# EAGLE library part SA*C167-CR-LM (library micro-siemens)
16 bit Microcontroller
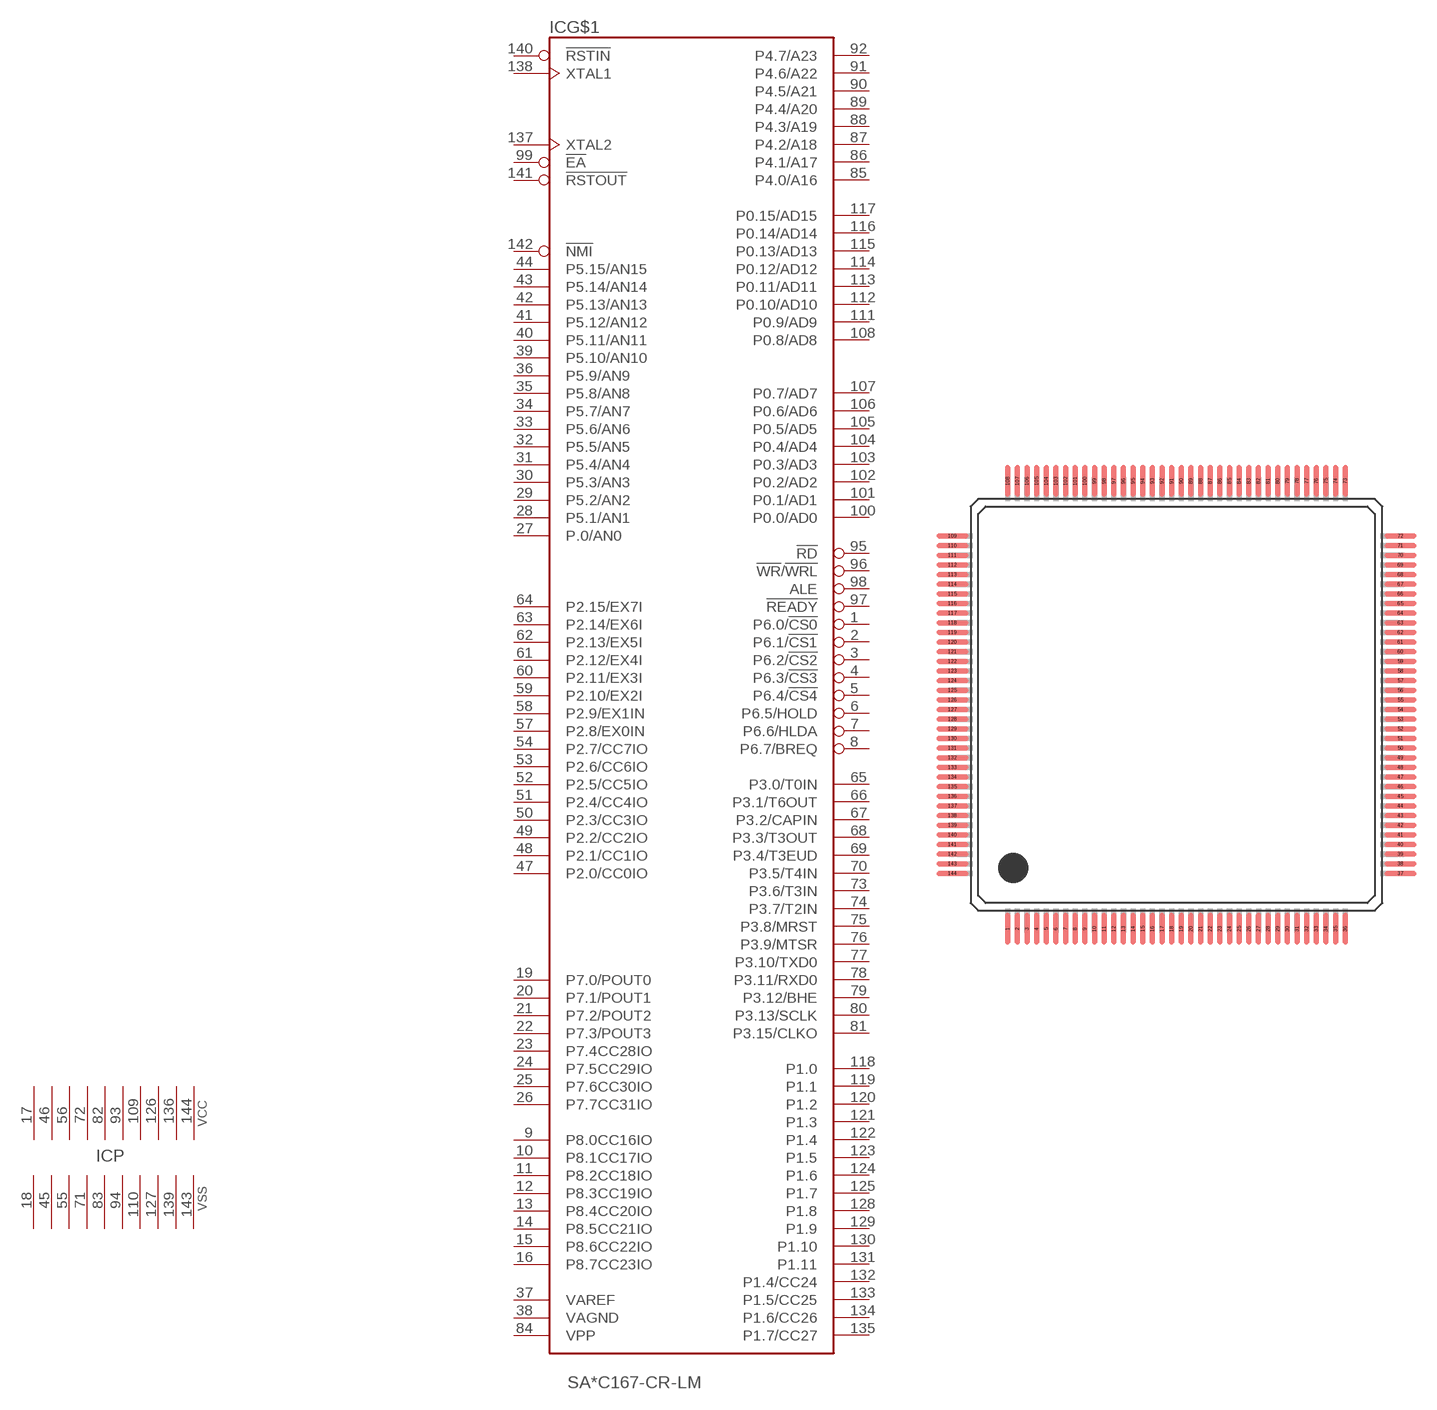
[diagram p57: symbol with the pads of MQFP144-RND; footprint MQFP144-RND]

Designator prefix IC; gates G$1=C167-2 P=10VCCVSS-1

## SABC167-CR-LM (OC_FARNELL: unknown; OC_NEWARK: unknown), SAFC167-CR-LM (OC_FARNELL: unknown; OC_NEWARK: unknown), SAKC167-CR-LM (OC_FARNELL: unknown; OC_NEWARK: unknown)  [MQFP144-RND]
1  G$1:P6.0/!CS0
2  G$1:P6.1/!CS1
3  G$1:P6.2/!CS2
4  G$1:P6.3/!CS3
5  G$1:P6.4/!CS4
6  G$1:P6.5/HOLD
7  G$1:P6.6/HLDA
8  G$1:P6.7/BREQ
9  G$1:P8.0CC16IO
10  G$1:P8.1CC17IO
11  G$1:P8.2CC18IO
12  G$1:P8.3CC19IO
13  G$1:P8.4CC20IO
14  G$1:P8.5CC21IO
15  G$1:P8.6CC22IO
16  G$1:P8.7CC23IO
17  P:VCC  pwr
18  P:VSS  pwr
19  G$1:P7.0/POUT0
20  G$1:P7.1/POUT1
21  G$1:P7.2/POUT2
22  G$1:P7.3/POUT3
23  G$1:P7.4CC28IO
24  G$1:P7.5CC29IO
25  G$1:P7.6CC30IO
26  G$1:P7.7CC31IO
27  G$1:P.0/AN0  in
28  G$1:P5.1/AN1  in
29  G$1:P5.2/AN2  in
30  G$1:P5.3/AN3  in
31  G$1:P5.4/AN4  in
32  G$1:P5.5/AN5  in
33  G$1:P5.6/AN6  in
34  G$1:P5.7/AN7  in
35  G$1:P5.8/AN8  in
36  G$1:P5.9/AN9  in
37  G$1:VAREF  pas
38  G$1:VAGND  pas
39  G$1:P5.10/AN10  in
40  G$1:P5.11/AN11  in
41  G$1:P5.12/AN12  in
42  G$1:P5.13/AN13  in
43  G$1:P5.14/AN14  in
44  G$1:P5.15/AN15  in
45  P:VSS  pwr
46  P:VCC  pwr
47  G$1:P2.0/CC0IO
48  G$1:P2.1/CC1IO
49  G$1:P2.2/CC2IO
50  G$1:P2.3/CC3IO
51  G$1:P2.4/CC4IO
52  G$1:P2.5/CC5IO
53  G$1:P2.6/CC6IO
54  G$1:P2.7/CC7IO
55  P:VSS  pwr
56  P:VCC  pwr
57  G$1:P2.8/EX0IN
58  G$1:P2.9/EX1IN
59  G$1:P2.10/EX2I
60  G$1:P2.11/EX3I
61  G$1:P2.12/EX4I
62  G$1:P2.13/EX5I
63  G$1:P2.14/EX6I
64  G$1:P2.15/EX7I
65  G$1:P3.0/T0IN
66  G$1:P3.1/T6OUT
67  G$1:P3.2/CAPIN
68  G$1:P3.3/T3OUT
69  G$1:P3.4/T3EUD
70  G$1:P3.5/T4IN
71  P:VSS  pwr
72  P:VCC  pwr
73  G$1:P3.6/T3IN
74  G$1:P3.7/T2IN
75  G$1:P3.8/MRST
76  G$1:P3.9/MTSR
77  G$1:P3.10/TXD0
78  G$1:P3.11/RXD0
79  G$1:P3.12/BHE
80  G$1:P3.13/SCLK
81  G$1:P3.15/CLKO
82  P:VCC  pwr
83  P:VSS  pwr
84  G$1:VPP  pas
85  G$1:P4.0/A16
86  G$1:P4.1/A17
87  G$1:P4.2/A18
88  G$1:P4.3/A19
89  G$1:P4.4/A20
90  G$1:P4.5/A21
91  G$1:P4.6/A22
92  G$1:P4.7/A23
93  P:VCC  pwr
94  P:VSS  pwr
95  G$1:!RD  out
96  G$1:!WR!/!WRL  out
97  G$1:!READY  in
98  G$1:ALE  out
99  G$1:!EA  in
100  G$1:P0.0/AD0
101  G$1:P0.1/AD1
102  G$1:P0.2/AD2
103  G$1:P0.3/AD3
104  G$1:P0.4/AD4
105  G$1:P0.5/AD5
106  G$1:P0.6/AD6
107  G$1:P0.7/AD7
108  G$1:P0.8/AD8
109  P:VCC  pwr
110  P:VSS  pwr
111  G$1:P0.9/AD9
112  G$1:P0.10/AD10
113  G$1:P0.11/AD11
114  G$1:P0.12/AD12
115  G$1:P0.13/AD13
116  G$1:P0.14/AD14
117  G$1:P0.15/AD15
118  G$1:P1.0
119  G$1:P1.1
120  G$1:P1.2
121  G$1:P1.3
122  G$1:P1.4
123  G$1:P1.5
124  G$1:P1.6
125  G$1:P1.7
126  P:VCC  pwr
127  P:VSS  pwr
128  G$1:P1.8
129  G$1:P1.9
130  G$1:P1.10
131  G$1:P1.11
132  G$1:P1.4/CC24
133  G$1:P1.5/CC25
134  G$1:P1.6/CC26
135  G$1:P1.7/CC27
136  P:VCC  pwr
137  G$1:XTAL2  out
138  G$1:XTAL1  in
139  P:VSS  pwr
140  G$1:!RSTIN  in
141  G$1:!RSTOUT  out
142  G$1:!NMI  in
143  P:VSS  pwr
144  P:VCC  pwr

## Footprint MQFP144-RND (pad centres in mm)
Metric Quad Flat Pack with rounded pads
smd 0.35 x 2.2: 1 -11.375,-15.1; 2 -10.725,-15.1; 3 -10.075,-15.1; 4 -9.425,-15.1; 5 -8.775,-15.1; 6 -8.125,-15.1; 7 -7.475,-15.1; 8 -6.825,-15.1; 9 -6.175,-15.1; 10 -5.525,-15.1; 11 -4.875,-15.1; 12 -4.225,-15.1; 13 -3.575,-15.1; 14 -2.925,-15.1; 15 -2.275,-15.1; 16 -1.625,-15.1; 17 -0.975,-15.1; 18 -0.325,-15.1; 19 0.325,-15.1; 20 0.975,-15.1; 21 1.625,-15.1; 22 2.275,-15.1; 23 2.925,-15.1; 24 3.575,-15.1; 25 4.225,-15.1; 26 4.875,-15.1; 27 5.525,-15.1; 28 6.175,-15.1; 29 6.825,-15.1; 30 7.475,-15.1; 31 8.125,-15.1; 32 8.775,-15.1; 33 9.425,-15.1; 34 10.075,-15.1; 35 10.725,-15.1; 36 11.375,-15.1; 73 11.375,15.1; 74 10.725,15.1; 75 10.075,15.1; 76 9.425,15.1; 77 8.775,15.1; 78 8.125,15.1; 79 7.475,15.1; 80 6.825,15.1; 81 6.175,15.1; 82 5.525,15.1; 83 4.875,15.1; 84 4.225,15.1; 85 3.575,15.1; 86 2.925,15.1; 87 2.275,15.1; 88 1.625,15.1; 89 0.975,15.1; 90 0.325,15.1; 91 -0.325,15.1; 92 -0.975,15.1; 93 -1.625,15.1; 94 -2.275,15.1; 95 -2.925,15.1; 96 -3.575,15.1; 97 -4.225,15.1; 98 -4.875,15.1; 99 -5.525,15.1; 100 -6.175,15.1; 101 -6.825,15.1; 102 -7.475,15.1; 103 -8.125,15.1; 104 -8.775,15.1; 105 -9.425,15.1; 106 -10.075,15.1; 107 -10.725,15.1; 108 -11.375,15.1
smd 2.2 x 0.35: 37 15.1,-11.375; 38 15.1,-10.725; 39 15.1,-10.075; 40 15.1,-9.425; 41 15.1,-8.775; 42 15.1,-8.125; 43 15.1,-7.475; 44 15.1,-6.825; 45 15.1,-6.175; 46 15.1,-5.525; 47 15.1,-4.875; 48 15.1,-4.225; 49 15.1,-3.575; 50 15.1,-2.925; 51 15.1,-2.275; 52 15.1,-1.625; 53 15.1,-0.975; 54 15.1,-0.325; 55 15.1,0.325; 56 15.1,0.975; 57 15.1,1.625; 58 15.1,2.275; 59 15.1,2.925; 60 15.1,3.575; 61 15.1,4.225; 62 15.1,4.875; 63 15.1,5.525; 64 15.1,6.175; 65 15.1,6.825; 66 15.1,7.475; 67 15.1,8.125; 68 15.1,8.775; 69 15.1,9.425; 70 15.1,10.075; 71 15.1,10.725; 72 15.1,11.375; 109 -15.1,11.375; 110 -15.1,10.725; 111 -15.1,10.075; 112 -15.1,9.425; 113 -15.1,8.775; 114 -15.1,8.125; 115 -15.1,7.475; 116 -15.1,6.825; 117 -15.1,6.175; 118 -15.1,5.525; 119 -15.1,4.875; 120 -15.1,4.225; 121 -15.1,3.575; 122 -15.1,2.925; 123 -15.1,2.275; 124 -15.1,1.625; 125 -15.1,0.975; 126 -15.1,0.325; 127 -15.1,-0.325; 128 -15.1,-0.975; 129 -15.1,-1.625; 130 -15.1,-2.275; 131 -15.1,-2.925; 132 -15.1,-3.575; 133 -15.1,-4.225; 134 -15.1,-4.875; 135 -15.1,-5.525; 136 -15.1,-6.175; 137 -15.1,-6.825; 138 -15.1,-7.475; 139 -15.1,-8.125; 140 -15.1,-8.775; 141 -15.1,-9.425; 142 -15.1,-10.075; 143 -15.1,-10.725; 144 -15.1,-11.375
